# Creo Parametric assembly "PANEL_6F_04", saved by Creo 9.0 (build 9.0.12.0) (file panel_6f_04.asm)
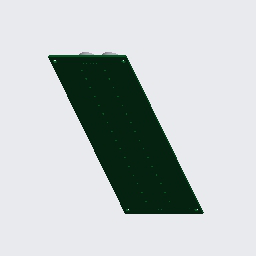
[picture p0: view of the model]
Units: millimeter Newton Second (mmNs); MM, TONNE, SECS

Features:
  1. coordinate system "PANEL_6F_04"
  2. imported feature "Import Feature id 4"
  3. component "PCB_6F"
  4. component "TX_6F_T1"
  5. component "TX_6F_T1"
  6. component "TX_6F_T1"
  7. component "TX_6F_T1"
  8. component "TX_6F_T1"
  9. component "TX_6F_T1"
  10. component "TX_6F_T1"
  11. component "TX_6F_T1"
  12. component "TX_6F_T1"
  13. component "TX_6F_T1"
  14. component "TX_6F_T1"
  15. component "TX_6F_T1"
  16. component "TX_6F_T1"
  17. component "TX_6F_T1"
  18. component "TX_6F_T1"
  19. component "TX_6F_T1"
